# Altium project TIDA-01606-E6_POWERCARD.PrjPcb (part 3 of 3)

## Sheet TIDA-01606-E6_POWERCARD_Voltage Sensing_Pg4.SchDoc
size 431 x 279 mm; Date: Not shown in title block; ApprovedBy: Not shown in title block; CheckedBy: Not shown in title block; Author: Not shown in title block; CompanyName: Not shown in title block; DrawnBy: Murali P; Engineer: Not shown in title block; Organization: Not shown in title block; Address1: Not shown in title block; Address2: Not shown in title block; Address3: Not shown in title block; Address4: Not shown in title block; DocumentNumber: 1; Revision: Use project parameter SCH_Rev; SheetNumber: 4; SheetTotal: 7; PageSetup: Record=PageOptions¦CenterHorizontal=True¦CenterVertical=True¦PrintScale=1.00¦XCorrection=1.00¦YCorrection=1.00¦PrintKind=0¦BorderSize=5000000¦LeftOffset=0¦BottomOffset=0¦Orientation=2¦PaperLength=1000¦PaperWidth=1000¦Scale=100¦PaperSource=15¦PrintQuality=600¦MediaType=1¦DitherType=10¦PaperKind=Letter¦PrintScaleMode=1
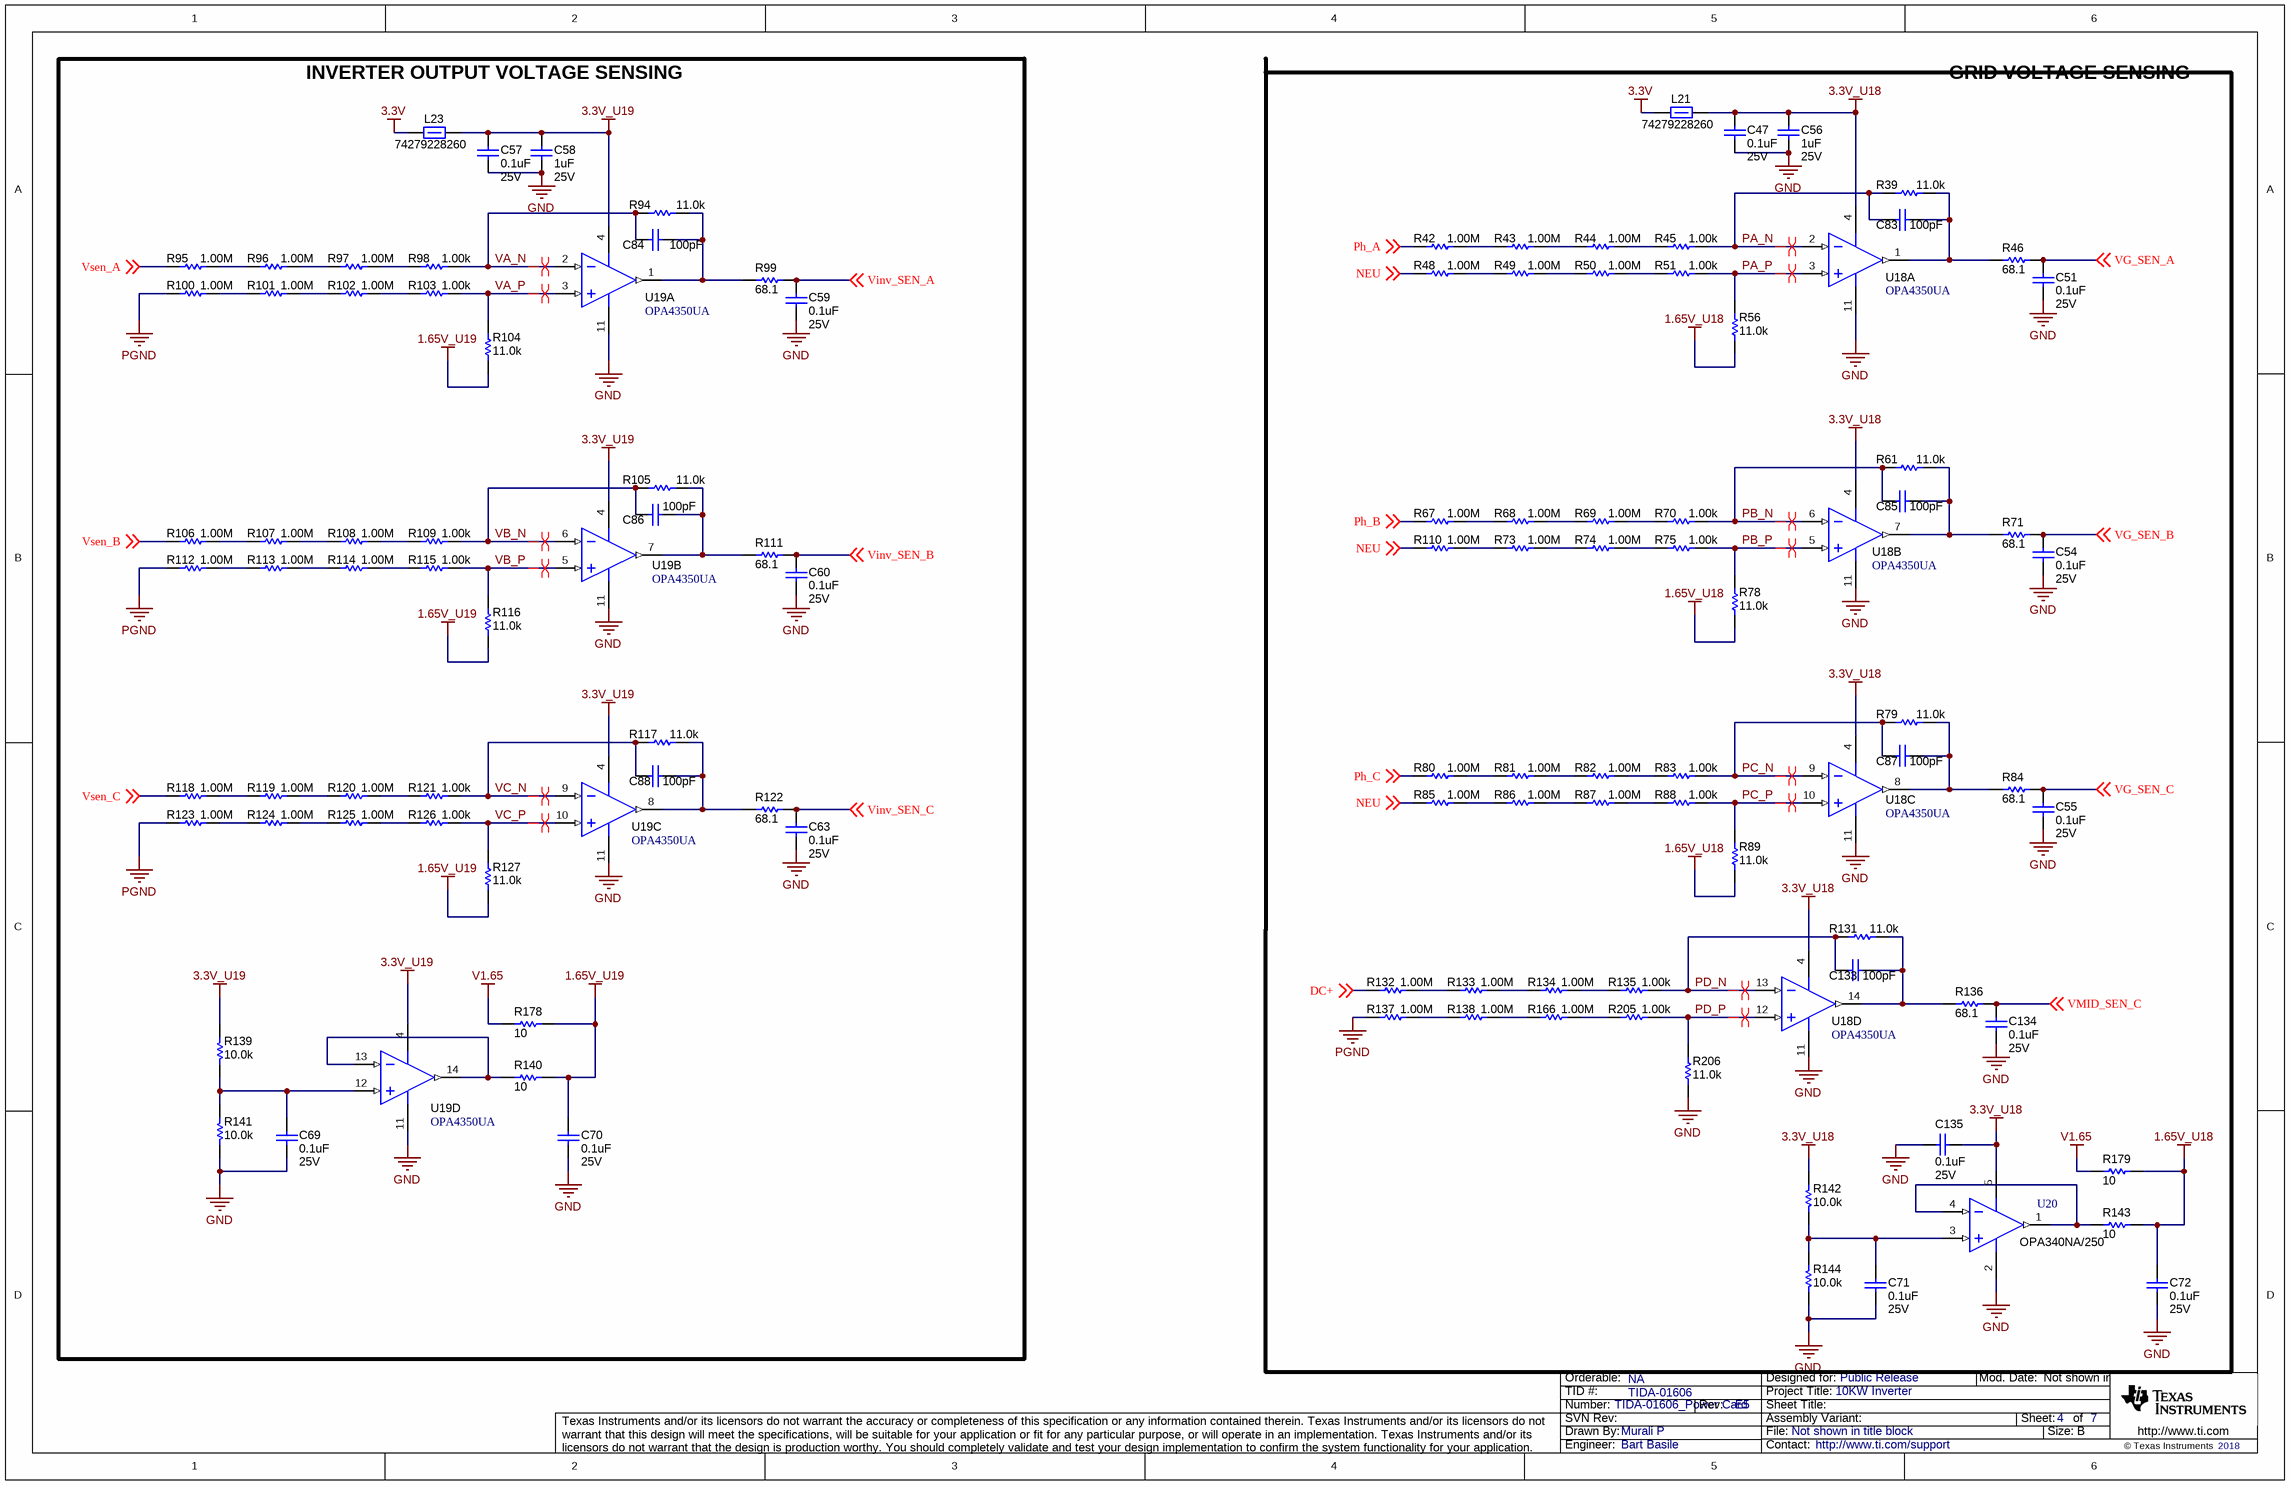
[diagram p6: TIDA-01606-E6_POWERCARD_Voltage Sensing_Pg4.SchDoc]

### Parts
C47  ValueDisplayed: 0.1uF  VDC_V: 25V  [0603]  (hidden comment: C0603X104K3RACTU)
C51  ValueDisplayed: 0.1uF  VDC_V: 25V  [0603]  (hidden comment: C0603X104K3RACTU)
C54  ValueDisplayed: 0.1uF  VDC_V: 25V  [0603]  (hidden comment: C0603X104K3RACTU)
C55  ValueDisplayed: 0.1uF  VDC_V: 25V  [0603]  (hidden comment: C0603X104K3RACTU)
C56  ValueDisplayed: 1uF  VDC_V: 25V  [0603]  (hidden comment: C0603C105K3RACTU)
C57  ValueDisplayed: 0.1uF  VDC_V: 25V  [0603]  (hidden comment: C0603X104K3RACTU)
C58  ValueDisplayed: 1uF  VDC_V: 25V  [0603]  (hidden comment: C0603C105K3RACTU)
C59  ValueDisplayed: 0.1uF  VDC_V: 25V  [0603]  (hidden comment: C0603X104K3RACTU)
C60  ValueDisplayed: 0.1uF  VDC_V: 25V  [0603]  (hidden comment: C0603X104K3RACTU)
C63  ValueDisplayed: 0.1uF  VDC_V: 25V  [0603]  (hidden comment: C0603X104K3RACTU)
C69  ValueDisplayed: 0.1uF  VDC_V: 25V  [0603]  (hidden comment: C0603X104K3RACTU)
C70  ValueDisplayed: 0.1uF  VDC_V: 25V  [0603]  (hidden comment: C0603X104K3RACTU)
C71  ValueDisplayed: 0.1uF  VDC_V: 25V  [0603]  (hidden comment: C0603X104K3RACTU)
C72  ValueDisplayed: 0.1uF  VDC_V: 25V  [0603]  (hidden comment: C0603X104K3RACTU)
C83  ValueDisplayed: 100pF  [0603]  (hidden comment: 06035A101FAT2A)
C84  ValueDisplayed: 100pF  [0603]  (hidden comment: 06035A101FAT2A)
C85  ValueDisplayed: 100pF  [0603]  (hidden comment: 06035A101FAT2A)
C86  ValueDisplayed: 100pF  [0603]  (hidden comment: 06035A101FAT2A)
C87  ValueDisplayed: 100pF  [0603]  (hidden comment: 06035A101FAT2A)
C88  ValueDisplayed: 100pF  [0603]  (hidden comment: 06035A101FAT2A)
C133  ValueDisplayed: 100pF  [0603]  (hidden comment: 06035A101FAT2A)
C134  ValueDisplayed: 0.1uF  VDC_V: 25V  [0603]  (hidden comment: C0603X104K3RACTU)
C135  ValueDisplayed: 0.1uF  VDC_V: 25V  [0603]  (hidden comment: C0603X104K3RACTU)
L21  74279228260  [0603]
L23  74279228260  [0603]
R39  ValueDisplayed: 11.0k  [0805_HV]  (hidden comment: RG2012P-113-B-T5)
R42  ValueDisplayed: 1.00M  [0805_HV]  (hidden comment: RT0805BRD071ML)
R43  ValueDisplayed: 1.00M  [0805_HV]  (hidden comment: RT0805BRD071ML)
R44  ValueDisplayed: 1.00M  [0805_HV]  (hidden comment: RT0805BRD071ML)
R45  ValueDisplayed: 1.00k  [0805_HV]  (hidden comment: RT0805BRD071KL)
R46  ValueDisplayed: 68.1  [0603]  (hidden comment: CRCW060368R1FKEA)
R48  ValueDisplayed: 1.00M  [0805_HV]  (hidden comment: RT0805BRD071ML)
R49  ValueDisplayed: 1.00M  [0805_HV]  (hidden comment: RT0805BRD071ML)
R50  ValueDisplayed: 1.00M  [0805_HV]  (hidden comment: RT0805BRD071ML)
R51  ValueDisplayed: 1.00k  [0805_HV]  (hidden comment: RT0805BRD071KL)
R56  ValueDisplayed: 11.0k  [0805_HV]  (hidden comment: RG2012P-113-B-T5)
R61  ValueDisplayed: 11.0k  [0805_HV]  (hidden comment: RG2012P-113-B-T5)
R67  ValueDisplayed: 1.00M  [0805_HV]  (hidden comment: RT0805BRD071ML)
R68  ValueDisplayed: 1.00M  [0805_HV]  (hidden comment: RT0805BRD071ML)
R69  ValueDisplayed: 1.00M  [0805_HV]  (hidden comment: RT0805BRD071ML)
R70  ValueDisplayed: 1.00k  [0805_HV]  (hidden comment: RT0805BRD071KL)
R71  ValueDisplayed: 68.1  [0603]  (hidden comment: CRCW060368R1FKEA)
R73  ValueDisplayed: 1.00M  [0805_HV]  (hidden comment: RT0805BRD071ML)
R74  ValueDisplayed: 1.00M  [0805_HV]  (hidden comment: RT0805BRD071ML)
R75  ValueDisplayed: 1.00k  [0805_HV]  (hidden comment: RT0805BRD071KL)
R78  ValueDisplayed: 11.0k  [0805_HV]  (hidden comment: RG2012P-113-B-T5)
R79  ValueDisplayed: 11.0k  [0805_HV]  (hidden comment: RG2012P-113-B-T5)
R80  ValueDisplayed: 1.00M  [0805_HV]  (hidden comment: RT0805BRD071ML)
R81  ValueDisplayed: 1.00M  [0805_HV]  (hidden comment: RT0805BRD071ML)
R82  ValueDisplayed: 1.00M  [0805_HV]  (hidden comment: RT0805BRD071ML)
R83  ValueDisplayed: 1.00k  [0805_HV]  (hidden comment: RT0805BRD071KL)
R84  ValueDisplayed: 68.1  [0603]  (hidden comment: CRCW060368R1FKEA)
R85  ValueDisplayed: 1.00M  [0805_HV]  (hidden comment: RT0805BRD071ML)
R86  ValueDisplayed: 1.00M  [0805_HV]  (hidden comment: RT0805BRD071ML)
R87  ValueDisplayed: 1.00M  [0805_HV]  (hidden comment: RT0805BRD071ML)
R88  ValueDisplayed: 1.00k  [0805_HV]  (hidden comment: RT0805BRD071KL)
R89  ValueDisplayed: 11.0k  [0805_HV]  (hidden comment: RG2012P-113-B-T5)
R94  ValueDisplayed: 11.0k  [0805_HV]  (hidden comment: RG2012P-113-B-T5)
R95  ValueDisplayed: 1.00M  [0805_HV]  (hidden comment: RT0805BRD071ML)
R96  ValueDisplayed: 1.00M  [0805_HV]  (hidden comment: RT0805BRD071ML)
R97  ValueDisplayed: 1.00M  [0805_HV]  (hidden comment: RT0805BRD071ML)
R98  ValueDisplayed: 1.00k  [0805_HV]  (hidden comment: RT0805BRD071KL)
R99  ValueDisplayed: 68.1  [0603]  (hidden comment: CRCW060368R1FKEA)
R100  ValueDisplayed: 1.00M  [0805_HV]  (hidden comment: RT0805BRD071ML)
R101  ValueDisplayed: 1.00M  [0805_HV]  (hidden comment: RT0805BRD071ML)
R102  ValueDisplayed: 1.00M  [0805_HV]  (hidden comment: RT0805BRD071ML)
R103  ValueDisplayed: 1.00k  [0805_HV]  (hidden comment: RT0805BRD071KL)
R104  ValueDisplayed: 11.0k  [0805_HV]  (hidden comment: RG2012P-113-B-T5)
R105  ValueDisplayed: 11.0k  [0805_HV]  (hidden comment: RG2012P-113-B-T5)
R106  ValueDisplayed: 1.00M  [0805_HV]  (hidden comment: RT0805BRD071ML)
R107  ValueDisplayed: 1.00M  [0805_HV]  (hidden comment: RT0805BRD071ML)
R108  ValueDisplayed: 1.00M  [0805_HV]  (hidden comment: RT0805BRD071ML)
R109  ValueDisplayed: 1.00k  [0805_HV]  (hidden comment: RT0805BRD071KL)
R110  ValueDisplayed: 1.00M  [0805_HV]  (hidden comment: RT0805BRD071ML)
R111  ValueDisplayed: 68.1  [0603]  (hidden comment: CRCW060368R1FKEA)
R112  ValueDisplayed: 1.00M  [0805_HV]  (hidden comment: RT0805BRD071ML)
R113  ValueDisplayed: 1.00M  [0805_HV]  (hidden comment: RT0805BRD071ML)
R114  ValueDisplayed: 1.00M  [0805_HV]  (hidden comment: RT0805BRD071ML)
R115  ValueDisplayed: 1.00k  [0805_HV]  (hidden comment: RT0805BRD071KL)
R116  ValueDisplayed: 11.0k  [0805_HV]  (hidden comment: RG2012P-113-B-T5)
R117  ValueDisplayed: 11.0k  [0805_HV]  (hidden comment: RG2012P-113-B-T5)
R118  ValueDisplayed: 1.00M  [0805_HV]  (hidden comment: RT0805BRD071ML)
R119  ValueDisplayed: 1.00M  [0805_HV]  (hidden comment: RT0805BRD071ML)
R120  ValueDisplayed: 1.00M  [0805_HV]  (hidden comment: RT0805BRD071ML)
R121  ValueDisplayed: 1.00k  [0805_HV]  (hidden comment: RT0805BRD071KL)
R122  ValueDisplayed: 68.1  [0603]  (hidden comment: CRCW060368R1FKEA)
R123  ValueDisplayed: 1.00M  [0805_HV]  (hidden comment: RT0805BRD071ML)
R124  ValueDisplayed: 1.00M  [0805_HV]  (hidden comment: RT0805BRD071ML)
R125  ValueDisplayed: 1.00M  [0805_HV]  (hidden comment: RT0805BRD071ML)
R126  ValueDisplayed: 1.00k  [0805_HV]  (hidden comment: RT0805BRD071KL)
R127  ValueDisplayed: 11.0k  [0805_HV]  (hidden comment: RG2012P-113-B-T5)
R131  ValueDisplayed: 11.0k  [0805_HV]  (hidden comment: RG2012P-113-B-T5)
R132  ValueDisplayed: 1.00M  [0805_HV]  (hidden comment: RT0805BRD071ML)
R133  ValueDisplayed: 1.00M  [0805_HV]  (hidden comment: RT0805BRD071ML)
R134  ValueDisplayed: 1.00M  [0805_HV]  (hidden comment: RT0805BRD071ML)
R135  ValueDisplayed: 1.00k  [0805_HV]  (hidden comment: RT0805BRD071KL)
R136  ValueDisplayed: 68.1  [0603]  (hidden comment: CRCW060368R1FKEA)
R137  ValueDisplayed: 1.00M  [0805_HV]  (hidden comment: RT0805BRD071ML)
R138  ValueDisplayed: 1.00M  [0805_HV]  (hidden comment: RT0805BRD071ML)
R139  ValueDisplayed: 10.0k  [0603]  (hidden comment: RG1608P-103-B-T5)
R140  ValueDisplayed: 10  [0603]  (hidden comment: CRCW060310R0JNEA)
R141  ValueDisplayed: 10.0k  [0603]  (hidden comment: RG1608P-103-B-T5)
R142  ValueDisplayed: 10.0k  [0603]  (hidden comment: RG1608P-103-B-T5)
R143  ValueDisplayed: 10  [0603]  (hidden comment: CRCW060310R0JNEA)
R144  ValueDisplayed: 10.0k  [0603]  (hidden comment: RG1608P-103-B-T5)
R166  ValueDisplayed: 1.00M  [0805_HV]  (hidden comment: RT0805BRD071ML)
R178  ValueDisplayed: 10  [0603]  (hidden comment: CRCW060310R0JNEA)
R179  ValueDisplayed: 10  [0603]  (hidden comment: CRCW060310R0JNEA)
R205  ValueDisplayed: 1.00k  [0805_HV]  (hidden comment: RT0805BRD071KL)
R206  ValueDisplayed: 11.0k  [0805_HV]  (hidden comment: RG2012P-113-B-T5)
U18  OPA4350UA  [D0014A_N]  (parts A,B,C,D of 4)
U19  OPA4350UA  [D0014A_N]  (parts A,B,C,D of 4)
U20  OPA340NA/250  [DBV0005A_N]

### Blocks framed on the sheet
INVERTER OUTPUT VOLTAGE SENSING: C57-C60 C63 C69 C70 C84 C86 C88 L23 R94-R109 R111-R127 R139-R141 R178 U19

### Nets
1.65V_U18: C72.2 R56.1 R78.1 R89.1 R143.2 R179.1
1.65V_U19: C70.2 R104.1 R116.1 R127.1 R140.2 R178.1
3.3V: L21.1 L23.1
3.3V_U18: C47.2 C56.1 C135.2 L21.2 R142.1 U18.4(V+) U20.5(V+)
3.3V_U19: C57.2 C58.1 L23.2 R139.1 U19.4(V+)
GND: C47.1 C51.1 C54.1 C55.1 C56.2 C57.1 C58.2 C59.1 C60.1 C63.1 C69.1 C70.1 C71.1 C72.1 C134.1 C135.1 R141.2 R144.2 R206.1 U18.11(V-) U19.11(V-) U20.2(V-)
PGND: R100.1 R112.1 R123.1 R137.1
V1.65: R178.2 R179.2
DC+: R132.1 ; off-sheet DC+
NEU: R48.1 R85.1 R110.1 ; off-sheet NEU
PA_N: C83.2 R39.2 R45.2 U18.2(IN_A-)
PA_P: R51.2 R56.2 U18.3(IN_A+)
PB_N: C85.2 R61.2 R70.2 U18.6(IN_B-)
PB_P: R75.2 R78.2 U18.5(IN_B+)
PC_N: C87.2 R79.2 R83.2 U18.9(IN_C-)
PC_P: R88.2 R89.2 U18.10(IN_C+)
PD_N: C133.2 R131.2 R135.2 U18.13(IN_D-)
PD_P: R205.2 R206.2 U18.12(IN_D+)
Ph_A: R42.1 ; off-sheet Ph_A
Ph_B: R67.1 ; off-sheet Ph_B
Ph_C: R80.1 ; off-sheet Ph_C
VA_N: C84.2 R94.2 R98.2 U19.2(IN_A-)
VA_P: R103.2 R104.2 U19.3(IN_A+)
VB_N: C86.2 R105.2 R109.2 U19.6(IN_B-)
VB_P: R115.2 R116.2 U19.5(IN_B+)
VC_N: C88.2 R117.2 R121.2 U19.9(IN_C-)
VC_P: R126.2 R127.2 U19.10(IN_C+)
VG_SEN_A: C51.2 R46.2 ; off-sheet VG_SEN_A
VG_SEN_B: C54.2 R71.2 ; off-sheet VG_SEN_B
VG_SEN_C: C55.2 R84.2 ; off-sheet VG_SEN_C
Vinv_SEN_A: C59.2 R99.2 ; off-sheet Vinv_SEN_A
Vinv_SEN_B: C60.2 R111.2 ; off-sheet Vinv_SEN_B
Vinv_SEN_C: C63.2 R122.2 ; off-sheet Vinv_SEN_C
VMID_SEN_C: C134.2 R136.2 ; off-sheet VMID_SEN_C
Vsen_A: R95.1 ; off-sheet Vsen_A
Vsen_B: R106.1 ; off-sheet Vsen_B
Vsen_C: R118.1 ; off-sheet Vsen_C
NetC69_2: C69.2 R139.2 R141.1 U19.12(IN_D+)
NetC71_2: C71.2 R142.2 R144.1 U20.3(IN+)
NetC83_1: C83.1 R39.1 R46.1 U18.1(OUT_A)
NetC84_1: C84.1 R94.1 R99.1 U19.1(OUT_A)
NetC85_1: C85.1 R61.1 R71.1 U18.7(OUT_B)
NetC86_1: C86.1 R105.1 R111.1 U19.7(OUT_B)
NetC87_1: C87.1 R79.1 R84.1 U18.8(OUT_C)
NetC88_1: C88.1 R117.1 R122.1 U19.8(OUT_C)
NetC133_1: C133.1 R131.1 R136.1 U18.14(OUT_D)
NetR42_2: R42.2 R43.1
NetR43_2: R43.2 R44.1
NetR44_2: R44.2 R45.1
NetR48_2: R48.2 R49.1
NetR49_2: R49.2 R50.1
NetR50_2: R50.2 R51.1
NetR67_2: R67.2 R68.1
NetR68_2: R68.2 R69.1
NetR69_2: R69.2 R70.1
NetR73_1: R73.1 R110.2
NetR73_2: R73.2 R74.1
NetR74_2: R74.2 R75.1
NetR80_2: R80.2 R81.1
NetR81_2: R81.2 R82.1
NetR82_2: R82.2 R83.1
NetR85_2: R85.2 R86.1
NetR86_2: R86.2 R87.1
NetR87_2: R87.2 R88.1
NetR95_2: R95.2 R96.1
NetR96_2: R96.2 R97.1
NetR97_2: R97.2 R98.1
NetR100_2: R100.2 R101.1
NetR101_2: R101.2 R102.1
NetR102_2: R102.2 R103.1
NetR106_2: R106.2 R107.1
NetR107_2: R107.2 R108.1
NetR108_2: R108.2 R109.1
NetR112_2: R112.2 R113.1
NetR113_2: R113.2 R114.1
NetR114_2: R114.2 R115.1
NetR118_2: R118.2 R119.1
NetR119_2: R119.2 R120.1
NetR120_2: R120.2 R121.1
NetR123_2: R123.2 R124.1
NetR124_2: R124.2 R125.1
NetR125_2: R125.2 R126.1
NetR132_2: R132.2 R133.1
NetR133_2: R133.2 R134.1
NetR134_2: R134.2 R135.1
NetR137_2: R137.2 R138.1
NetR138_2: R138.2 R166.1
NetR140_1: R140.1 U19.13(IN_D-) U19.14(OUT_D)
NetR143_1: R143.1 U20.1(OUT) U20.4(IN-)
NetR166_2: R166.2 R205.1

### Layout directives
differential pair: PA_N, PA_P, PB_N, PB_P, PC_N, PC_P, PD_N, PD_P, VA_N, VA_P, VB_N, VB_P, VC_N, VC_P

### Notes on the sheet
- GRID VOLTAGE SENSING

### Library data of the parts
C47 C51 C54 C55 C57 C59 C60 C63 C69-C72 C134 C135 = CMP-0006979-5: CAP, CERM, 0.1 uF, 25 V, +/- 10%, X7R, 0603; Manufacturer: Kemet; Polarized: N; Value: 0.1uF; U/M: EA; Cap_F: 100nF; Value1: Unknown; TaMin_C: -55°C; TaMax_C: 125°C; SizeArea_mm2: 1.28; SizeAreaWB_mm2: 4.68; SizeX_mm: 1.6; SizeY_mm: 0.8; SizeZ_mm: 1; AEC Category: Q200
C56 C58 = CMP-0006867-4: CAP, CERM, 1 uF, 25 V, +/- 10%, X7R, 0603; Manufacturer: Kemet; Polarized: N; Value: 1uF; U/M: EA; Cap_F: 1µF; Value1: Unknown; TaMin_C: -55°C; TaMax_C: 125°C; SizeArea_mm2: 1.28; SizeAreaWB_mm2: 4.68; SizeX_mm: 1.6; SizeY_mm: 0.8; SizeZ_mm: 1; AEC Category: Q200
C83-C88 C133 = CMP-0006762-4: CAP, CERM, 100 pF, 50 V, +/- 1%, C0G/NP0, 0603; Manufacturer: AVX; Polarized: N; Value: 100pF; U/M: EA; Value1: Unknown; VDC_V: 50V; TaMin_C: -55°C; TaMax_C: 125°C; SizeArea_mm2: 1.28; SizeAreaWB_mm2: 4.68; SizeX_mm: 1.6; SizeY_mm: 0.8; SizeZ_mm: 1; AEC Category: Q200
L21 L23 = CMP-0003155-2: Ferrite Bead, 26 ohm @ 100 MHz, 6.5 A, 0603; Manufacturer: Wurth Elektronik; Ztyp@1GHz_Ohm: 35.506; ZTyp@100MHz_Ohm: 26; SizeAreaWB_mm2: 4.68; DCR_ohm: 5m; Value1: 0.005 ohm; Value: 26 ohm; Imax_A: 6.5A; SizeZ_mm: 1; SizeX_mm: 1.6; SizeY_mm: 0.8; SizeArea_mm2: 1.28
R39 R56 R61 R78 R79 R89 R94 R104 R105 R116 R117 R127 R131 R206 = CMP-0018864-2: RES, 11.0 k, 0.1%, 0.125 W, 0805; Manufacturer: Susumu Co Ltd; Value: 11.0k; Res_ohm: 11k; Value_Code: 11k0; Power_W: 125mW; Value2: 0.125W; VDC_V: 100V; TempCo: 25 ppm/C; SizeArea_mm2: 2.5; SizeX_mm: 2; SizeY_mm: 1.25; SizeZ_mm: 1.45; EIA_Code: E192; U/M: EA; AEC Category: Q200
R42-R44 R48-R50 R67-R69 R73 R74 R80-R82 R85-R87 R95-R97 R100-R102 R106-R108 R110 R112-R114 R118-R120 R123-R125 R132-R134 R137 R138 R166 = CMP-0019761-2: RES, 1.00 M, 0.1%, 0.125 W, 0805; Manufacturer: Yageo America; Value: 1.00Meg; Res_ohm: 1M; Value_Code: 1M00; Power_W: 125mW; Value2: 0.125W; VDC_V: 150V; TempCo: 25 ppm/C; SizeArea_mm2: 2.5; SizeX_mm: 2; SizeY_mm: 1.25; SizeZ_mm: 1.45; EIA_Code: E192; U/M: EA; AEC Category: Q200
R45 R51 R70 R75 R83 R88 R98 R103 R109 R115 R121 R126 R135 R205 = CMP-0019726-2: RES, 1.00 k, 0.1%, 0.125 W, 0805; Manufacturer: Yageo America; Value: 1.00k; Res_ohm: 1k; Value_Code: 1k00; Power_W: 125mW; Value2: 0.125W; VDC_V: 150V; TempCo: 25 ppm/C; SizeArea_mm2: 2.5; SizeX_mm: 2; SizeY_mm: 1.25; SizeZ_mm: 1.45; EIA_Code: E192; U/M: EA; AEC Category: Q200
R46 R71 R84 R99 R111 R122 R136 = CMP-0022553-4: RES, 68.1, 1%, 0.1 W, AEC-Q200 Grade 0, 0603; Manufacturer: Vishay-Dale; Value: 68.1; Value_Code: 68R1; Power_W: 100mW; Value2: 0.1W; VDC_V: 75V; TempCo: 100 ppm/C; SizeArea_mm2: 1.28; SizeX_mm: 1.6; SizeY_mm: 0.8; SizeZ_mm: 1; EIA_Code: E96; AEC Category: Q200; AEC Qualified: Y; AEC Grade: 0
R139 R141 R142 R144 = CMP-0023404-3: RES, 10.0 k, 0.1%, 0.1 W, 0603; Manufacturer: Susumu Co Ltd; Value: 10.0k; Res_ohm: 10k; Value_Code: 10k0; Power_W: 100mW; Value2: 0.1W; VDC_V: 75V; TempCo: 25 ppm/C; SizeArea_mm2: 1.28; SizeX_mm: 1.6; SizeY_mm: 0.8; SizeZ_mm: 1; EIA_Code: E192; U/M: EA; AEC Category: Q200
R140 R143 R178 R179 = CMP-0025703-4: RES, 10, 5%, 0.1 W, AEC-Q200 Grade 0, 0603; Manufacturer: Vishay-Dale; Value: 10; Value_Code: 10R0; Power_W: 100mW; Value2: 0.1W; VDC_V: 75V; TempCo: 200 ppm/C; SizeArea_mm2: 1.28; SizeX_mm: 1.6; SizeY_mm: 0.8; SizeZ_mm: 1; EIA_Code: E24; AEC Category: Q200; AEC Qualified: Y; AEC Grade: 0
U18 U19 = CMP-0041149-1: High-Speed, Single-Supply, Rail-to-Rail Operational Amplifier MicroAmplifier(TM) Series, 2.7 to 5.5 V, -55 to 150 degC, 14-pin SOIC (D14), Green (RoHS & no Sb/Br); Manufacturer: Texas Instruments; CMRR(Min)(dB): 66; IIB(Max)(pA): 10; Iq per channel(Max)(mA): 7.5; Number of Channels: 4; Slew Rate(Typ)(V/us): 22; Sub Family: Low Input Bias Current Amp (<=10pA), Low Offset Voltage Amplifier (<=500uV), Low Supply Voltage Amplifier (<=2.7V), Precision Amplifier; Total Supply Voltage(Max)(+5V is 5, +/-5V is 10): 5.5; Total Supply Voltage(Min)(+5V is 5, +/-5V is 10): 2.7; Vio (25C)(Max)(mV): 0.5; Vn at 1kHz(Typ)(nV/rtHz): 18
U20 = CMP-0040936-1: Single-Supply, Rail-to-Rail Operational Amplifier MicroAmplifier(TM) Series, 2.7 to 5.5 V, -40 to 85 degC, 5-pin SOT23 (DBV5), Green (RoHS & no Sb/Br); Manufacturer: Texas Instruments; Total Supply Voltage(Min)(+5V is 5, +/-5V is 10): 2.7; Offset Drift(Typ)(uV/C): 2.5; Vn at 1kHz(Typ)(nV/rtHz): 25; Slew Rate(Typ)(V/us): 6; Number of Channels: 1; CMRR(Min)(dB): 80; Iq per channel(Max)(mA): 0.95; Total Supply Voltage(Max)(+5V is 5, +/-5V is 10): 5.5; IIB(Max)(pA): 10; Sub Family: Low Input Bias Current Amp (<=10pA), Low Offset Voltage Amplifier (<=500uV), Low Supply Voltage Amplifier (<=2.7V), Precision Amplifier; Vio (25C)(Max)(mV): 0.5

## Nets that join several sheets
1.65V_U18: TIDA-01606-E6_POWERCARD_Controller Card_Pg6 (R195.2), TIDA-01606-E6_POWERCARD_Voltage Sensing_Pg4 (6 pins)
1.65V_U19: TIDA-01606-E6_POWERCARD_Controller Card_Pg6 (R196.2), TIDA-01606-E6_POWERCARD_Voltage Sensing_Pg4 (6 pins)
3.3V: TIDA-01606-E6_POWERCARD_Controller Card_Pg6 (8 pins), TIDA-01606-E6_POWERCARD_Current Sensing_Pg5 (L7.1 L8.1 L13.1 L17.1), TIDA-01606-E6_POWERCARD_Power Supply and Protection_Pg3 (18 pins), TIDA-01606-E6_POWERCARD_Voltage Sensing_Pg4 (L21.1 L23.1)
5V: TIDA-01606-E6_POWERCARD_Controller Card_Pg6 (10 pins), TIDA-01606-E6_POWERCARD_Current Sensing_Pg5 (L9.1 L10.1 L14.1), TIDA-01606-E6_POWERCARD_Power Supply and Protection_Pg3 (9 pins)
5V_1: TIDA-01606-E6_POWERCARD_Current Sensing_Pg5 (C28.1 D12.3 U1.1), TIDA-01606-E6_POWERCARD_Power Supply and Protection_Pg3 (D28.1 R155.2 R156.2)
5V_2: TIDA-01606-E6_POWERCARD_Current Sensing_Pg5 (C35.1 D14.3 U5.1), TIDA-01606-E6_POWERCARD_Power Supply and Protection_Pg3 (D29.1 R157.2 R158.2)
5V_3: TIDA-01606-E6_POWERCARD_Current Sensing_Pg5 (C18.1 D16.3 U8.1), TIDA-01606-E6_POWERCARD_Power Supply and Protection_Pg3 (D33.1 R161.2 R162.2)
24V: TIDA-01606-E6_POWERCARD_Power Stage_Pg2 (TP2.1), TIDA-01606-E6_POWERCARD_Power Supply and Protection_Pg3 (J33.1 J33.1A J34.2 J39.2)
+12V: TIDA-01606-E6_POWERCARD_Controller Card_Pg6 (5 pins), TIDA-01606-E6_POWERCARD_Power Stage_Pg2 (8 pins), TIDA-01606-E6_POWERCARD_Power Supply and Protection_Pg3 (8 pins)
+24V_Gate_Boards: TIDA-01606-E6_POWERCARD_Controller Card_Pg6 (J23.7 J24.7 J25.7), TIDA-01606-E6_POWERCARD_Power Supply and Protection_Pg3 (J39.1)
GND: TIDA-01606-E6_POWERCARD_Controller Card_Pg6 (41 pins), TIDA-01606-E6_POWERCARD_Current Sensing_Pg5 (30 pins), TIDA-01606-E6_POWERCARD_Power Stage_Pg2 (10 pins), TIDA-01606-E6_POWERCARD_Power Supply and Protection_Pg3 (72 pins), TIDA-01606-E6_POWERCARD_Voltage Sensing_Pg4 (22 pins)
GND_AMC1: TIDA-01606-E6_POWERCARD_Current Sensing_Pg5 (C28.2 D13.3 R147.1 U1.4), TIDA-01606-E6_POWERCARD_Power Stage_Pg2 (K1.1 R5.2 RF1.2), TIDA-01606-E6_POWERCARD_Power Supply and Protection_Pg3 (12 pins)
GND_AMC2: TIDA-01606-E6_POWERCARD_Current Sensing_Pg5 (C35.2 D15.3 R150.1 U5.4), TIDA-01606-E6_POWERCARD_Power Stage_Pg2 (K2.1 R41.2 RF2.2), TIDA-01606-E6_POWERCARD_Power Supply and Protection_Pg3 (12 pins)
GND_AMC3: TIDA-01606-E6_POWERCARD_Current Sensing_Pg5 (C18.2 D17.3 R153.1 U8.4), TIDA-01606-E6_POWERCARD_Power Stage_Pg2 (K3.1 R47.2 RF3.2), TIDA-01606-E6_POWERCARD_Power Supply and Protection_Pg3 (12 pins)
PGND: TIDA-01606-E6_POWERCARD_Power Stage_Pg2 (49 pins), TIDA-01606-E6_POWERCARD_Voltage Sensing_Pg4 (R100.1 R112.1 R123.1 R137.1)
V1.65: TIDA-01606-E6_POWERCARD_Controller Card_Pg6 (C118.1 TP1.1 U24.1), TIDA-01606-E6_POWERCARD_Voltage Sensing_Pg4 (R178.2 R179.2)
DC+: TIDA-01606-E6_POWERCARD_Controller Card_Pg6 (J15.4 J16.4 J17.4), TIDA-01606-E6_POWERCARD_Power Stage_Pg2 (20 pins), TIDA-01606-E6_POWERCARD_Voltage Sensing_Pg4 (R132.1)
DC-: TIDA-01606-E6_POWERCARD_Controller Card_Pg6 (J9.2 J12.2 J20.2), TIDA-01606-E6_POWERCARD_Power Stage_Pg2 (23 pins)
Igrid_A: TIDA-01606-E6_POWERCARD_Current Sensing_Pg5 (R145.1), TIDA-01606-E6_POWERCARD_Power Stage_Pg2 (L2.2 R5.1)
Igrid_B: TIDA-01606-E6_POWERCARD_Current Sensing_Pg5 (R148.1), TIDA-01606-E6_POWERCARD_Power Stage_Pg2 (L4.2 R41.1)
Igrid_C: TIDA-01606-E6_POWERCARD_Current Sensing_Pg5 (R151.1), TIDA-01606-E6_POWERCARD_Power Stage_Pg2 (L6.2 R47.1)
Iind_A: TIDA-01606-E6_POWERCARD_Controller Card_Pg6 (J17.2 J20.4), TIDA-01606-E6_POWERCARD_Current Sensing_Pg5 (U3.1 U3.2 U3.3), TIDA-01606-E6_POWERCARD_Power Stage_Pg2 (Q1.3 Q2.2 Q3.2 R168.1)
Iind_A_Rtn: TIDA-01606-E6_POWERCARD_Current Sensing_Pg5 (U3.8 U3.9 U3.10), TIDA-01606-E6_POWERCARD_Power Stage_Pg2 (L1.2)
Iind_B: TIDA-01606-E6_POWERCARD_Controller Card_Pg6 (J9.4 J15.2), TIDA-01606-E6_POWERCARD_Current Sensing_Pg5 (U4.1 U4.2 U4.3), TIDA-01606-E6_POWERCARD_Power Stage_Pg2 (Q5.3 Q6.2 Q7.2 R169.1)
Iind_B_Rtn: TIDA-01606-E6_POWERCARD_Current Sensing_Pg5 (U4.8 U4.9 U4.10), TIDA-01606-E6_POWERCARD_Power Stage_Pg2 (L3.2)
Iind_C: TIDA-01606-E6_POWERCARD_Controller Card_Pg6 (J12.4 J16.2), TIDA-01606-E6_POWERCARD_Current Sensing_Pg5 (U6.1 U6.2 U6.3), TIDA-01606-E6_POWERCARD_Power Stage_Pg2 (Q9.3 Q10.2 Q11.2 R170.1)
Iind_C_Rtn: TIDA-01606-E6_POWERCARD_Current Sensing_Pg5 (U6.8 U6.9 U6.10), TIDA-01606-E6_POWERCARD_Power Stage_Pg2 (L5.2)
ILA_Fdbk: TIDA-01606-E6_POWERCARD_Controller Card_Pg6 (J5.25), TIDA-01606-E6_POWERCARD_Current Sensing_Pg5 (C41.2 R28.2)
ILB_Fdbk: TIDA-01606-E6_POWERCARD_Controller Card_Pg6 (J5.37), TIDA-01606-E6_POWERCARD_Current Sensing_Pg5 (C40.2 R27.2)
ILC_Fdbk: TIDA-01606-E6_POWERCARD_Controller Card_Pg6 (J5.34), TIDA-01606-E6_POWERCARD_Current Sensing_Pg5 (C45.2 R40.2)
NEU: TIDA-01606-E6_POWERCARD_Power Stage_Pg2 (J32.1 K4.2 RF4.1), TIDA-01606-E6_POWERCARD_Voltage Sensing_Pg4 (R48.1 R85.1 R110.1)
Ph_A: TIDA-01606-E6_POWERCARD_Power Stage_Pg2 (J3.1 K1.2 RF1.1), TIDA-01606-E6_POWERCARD_Voltage Sensing_Pg4 (R42.1)
Ph_B: TIDA-01606-E6_POWERCARD_Power Stage_Pg2 (J4.1 K2.2 RF2.1), TIDA-01606-E6_POWERCARD_Voltage Sensing_Pg4 (R67.1)
Ph_C: TIDA-01606-E6_POWERCARD_Power Stage_Pg2 (J31.1 K3.2 RF3.1), TIDA-01606-E6_POWERCARD_Voltage Sensing_Pg4 (R80.1)
Q1A: TIDA-01606-E6_POWERCARD_Controller Card_Pg6 (J17.1), TIDA-01606-E6_POWERCARD_Power Stage_Pg2 (Q1.1 R168.2)
Q1B: TIDA-01606-E6_POWERCARD_Controller Card_Pg6 (J15.1), TIDA-01606-E6_POWERCARD_Power Stage_Pg2 (Q5.1 R169.2)
Q1C: TIDA-01606-E6_POWERCARD_Controller Card_Pg6 (J16.1), TIDA-01606-E6_POWERCARD_Power Stage_Pg2 (Q9.1 R170.2)
Q2A: TIDA-01606-E6_POWERCARD_Controller Card_Pg6 (J20.1), TIDA-01606-E6_POWERCARD_Power Stage_Pg2 (Q2.1 R192.2)
Q2B: TIDA-01606-E6_POWERCARD_Controller Card_Pg6 (J9.1), TIDA-01606-E6_POWERCARD_Power Stage_Pg2 (Q6.1 R193.2)
Q2C: TIDA-01606-E6_POWERCARD_Controller Card_Pg6 (J12.1), TIDA-01606-E6_POWERCARD_Power Stage_Pg2 (Q10.1 R194.2)
Q3A: TIDA-01606-E6_POWERCARD_Controller Card_Pg6 (J14.1), TIDA-01606-E6_POWERCARD_Power Stage_Pg2 (Q3.1 R172.1)
Q3B: TIDA-01606-E6_POWERCARD_Controller Card_Pg6 (J18.1), TIDA-01606-E6_POWERCARD_Power Stage_Pg2 (Q7.1 R174.1)
Q3C: TIDA-01606-E6_POWERCARD_Controller Card_Pg6 (J19.1), TIDA-01606-E6_POWERCARD_Power Stage_Pg2 (Q11.1 R176.1)
Q4A: TIDA-01606-E6_POWERCARD_Controller Card_Pg6 (J7.1), TIDA-01606-E6_POWERCARD_Power Stage_Pg2 (Q4.1 R171.2)
Q4B: TIDA-01606-E6_POWERCARD_Controller Card_Pg6 (J21.1), TIDA-01606-E6_POWERCARD_Power Stage_Pg2 (Q8.1 R173.2)
Q4C: TIDA-01606-E6_POWERCARD_Controller Card_Pg6 (J22.1), TIDA-01606-E6_POWERCARD_Power Stage_Pg2 (Q12.1 R175.2)
QA_N: TIDA-01606-E6_POWERCARD_Controller Card_Pg6 (J7.2 J14.2), TIDA-01606-E6_POWERCARD_Power Stage_Pg2 (Q3.3 Q4.3 R171.1 R172.2)
QB_N: TIDA-01606-E6_POWERCARD_Controller Card_Pg6 (J18.2 J21.2), TIDA-01606-E6_POWERCARD_Power Stage_Pg2 (Q7.3 Q8.3 R173.1 R174.2)
QC_N: TIDA-01606-E6_POWERCARD_Controller Card_Pg6 (J19.2 J22.2), TIDA-01606-E6_POWERCARD_Power Stage_Pg2 (Q11.3 Q12.3 R175.1 R176.2)
RY_A: TIDA-01606-E6_POWERCARD_Controller Card_Pg6 (J5.86), TIDA-01606-E6_POWERCARD_Power Stage_Pg2 (R197.1)
RY_B: TIDA-01606-E6_POWERCARD_Controller Card_Pg6 (J5.88), TIDA-01606-E6_POWERCARD_Power Stage_Pg2 (R198.1)
RY_C: TIDA-01606-E6_POWERCARD_Controller Card_Pg6 (J5.90), TIDA-01606-E6_POWERCARD_Power Stage_Pg2 (R199.1)
RY_N: TIDA-01606-E6_POWERCARD_Controller Card_Pg6 (J5.92), TIDA-01606-E6_POWERCARD_Power Stage_Pg2 (R200.1)
SD_CLKI: TIDA-01606-E6_POWERCARD_Controller Card_Pg6 (5 pins), TIDA-01606-E6_POWERCARD_Current Sensing_Pg5 (U1.7 U5.7 U8.7)
SD_Data_IG_A: TIDA-01606-E6_POWERCARD_Controller Card_Pg6 (J5.99), TIDA-01606-E6_POWERCARD_Current Sensing_Pg5 (R146.2)
SD_Data_IG_B: TIDA-01606-E6_POWERCARD_Controller Card_Pg6 (J5.103), TIDA-01606-E6_POWERCARD_Current Sensing_Pg5 (R149.2)
SD_Data_IG_C: TIDA-01606-E6_POWERCARD_Controller Card_Pg6 (J5.107), TIDA-01606-E6_POWERCARD_Current Sensing_Pg5 (R152.2)
Temp_A: TIDA-01606-E6_POWERCARD_Controller Card_Pg6 (J5.12), TIDA-01606-E6_POWERCARD_Power Supply and Protection_Pg3 (C39.2 R52.2 R58.2)
TEMP_Amb: TIDA-01606-E6_POWERCARD_Controller Card_Pg6 (J5.20), TIDA-01606-E6_POWERCARD_Power Supply and Protection_Pg3 (C52.2 R93.2)
Temp_B: TIDA-01606-E6_POWERCARD_Controller Card_Pg6 (J5.14), TIDA-01606-E6_POWERCARD_Power Supply and Protection_Pg3 (C42.2 R62.2 R65.2)
Temp_C: TIDA-01606-E6_POWERCARD_Controller Card_Pg6 (J5.18), TIDA-01606-E6_POWERCARD_Power Supply and Protection_Pg3 (C50.2 R77.2 R92.2)
VG_SEN_A: TIDA-01606-E6_POWERCARD_Controller Card_Pg6 (J5.15), TIDA-01606-E6_POWERCARD_Voltage Sensing_Pg4 (C51.2 R46.2)
VG_SEN_B: TIDA-01606-E6_POWERCARD_Controller Card_Pg6 (J5.31), TIDA-01606-E6_POWERCARD_Voltage Sensing_Pg4 (C54.2 R71.2)
VG_SEN_C: TIDA-01606-E6_POWERCARD_Controller Card_Pg6 (J5.28), TIDA-01606-E6_POWERCARD_Voltage Sensing_Pg4 (C55.2 R84.2)
Vinv_SEN_A: TIDA-01606-E6_POWERCARD_Controller Card_Pg6 (J5.21), TIDA-01606-E6_POWERCARD_Voltage Sensing_Pg4 (C59.2 R99.2)
Vinv_SEN_B: TIDA-01606-E6_POWERCARD_Controller Card_Pg6 (J5.33), TIDA-01606-E6_POWERCARD_Voltage Sensing_Pg4 (C60.2 R111.2)
Vinv_SEN_C: TIDA-01606-E6_POWERCARD_Controller Card_Pg6 (J5.30), TIDA-01606-E6_POWERCARD_Voltage Sensing_Pg4 (C63.2 R122.2)
Vsen_A: TIDA-01606-E6_POWERCARD_Power Stage_Pg2 (C8.1 L1.1 L2.1), TIDA-01606-E6_POWERCARD_Voltage Sensing_Pg4 (R95.1)
Vsen_B: TIDA-01606-E6_POWERCARD_Power Stage_Pg2 (C9.1 L3.1 L4.1), TIDA-01606-E6_POWERCARD_Voltage Sensing_Pg4 (R106.1)
Vsen_C: TIDA-01606-E6_POWERCARD_Power Stage_Pg2 (C10.1 L5.1 L6.1), TIDA-01606-E6_POWERCARD_Voltage Sensing_Pg4 (R118.1)

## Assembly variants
001: not fitted C83 C84 C85 C86 C87 C88 C120 C121 C122 C127 C128 C129 D12 D13 D14 D15 D16 D17 FID1 FID2 FID3 FID4 FID5 FID6 R34 R140 R143 TP4 TP5 TP6 TP7 TP8 TP9 TP10 TP11 TP12
072318: not fitted C4 C5 C6 C7 C8 C9 C10 C73 C74 C75 C76 C83 C84 C85 C86 C87 C88 C120 C121 C122 C127 C128 C129 D12 D13 D14 D15 D16 D17 FID1 FID2 FID3 FID4 FID5 FID6 L1 L2 L3 L4 L5 L6 R34 R140 R143 TP4 TP5 TP6 TP7 TP8 TP9 TP10 TP11 TP12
